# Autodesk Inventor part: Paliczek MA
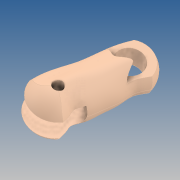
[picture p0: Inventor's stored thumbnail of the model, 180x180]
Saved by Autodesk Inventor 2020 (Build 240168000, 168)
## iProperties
Created: 2019-10
Part Number: Paliczek MA
Material: GFRP
Document SubType Name: Modeling
Designer: yello
Density: 1.75 g/cm^3
Appearance: Default
Author: yello
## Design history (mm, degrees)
feature "Paliczek MA"
sketch "Sketch1"
  geometry: C1 r 2 at (0, 0); 1 further point
  constraints: 1 centre point
  dimensions: "d0" = 4 diameter of C1
extrude "Extrusion1" cut sketch "Sketch1" stored distance "d1" = 100; taper "d2" = 0 deg
sketch "Sketch2"
  geometry: C1 r 5 at (0, 0); 1 further point
  constraints: 1 centre point
  dimensions: "d3" = 10 diameter of C1
extrude "Extrusion2" cut sketch "Sketch2" distance "d4" = 8; taper "d5" = 0 deg
body "Solid1"
